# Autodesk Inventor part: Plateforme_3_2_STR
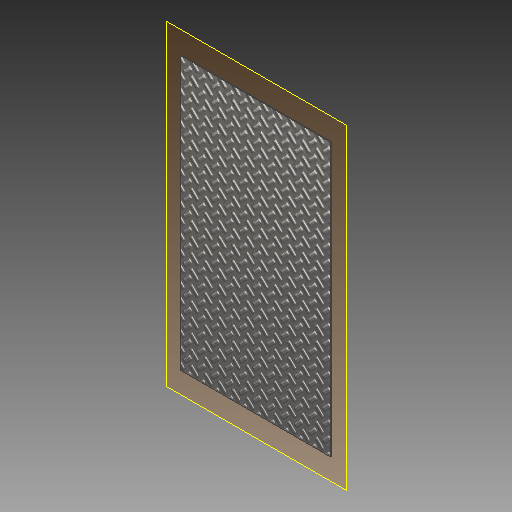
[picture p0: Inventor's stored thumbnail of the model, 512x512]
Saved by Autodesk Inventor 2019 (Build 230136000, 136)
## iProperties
Created: 2018-07
Part Number: Plateforme_3_2_STR
Material: Générique
Document SubType Name: Modeling
Designer: Fabian Perrée
Density: 1 g/cm^3
Appearance: Par défaut
Mass: 7553 g
Surface Area: 30469 cm^2
Volume: 7553 cm^3
Author: Fabian Perrée
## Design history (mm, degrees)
node "Plan de construction1"
sketch "Esquisse1"
  geometry: L1 (1000, 250)-(0, 250) reference; L2 (0, -1500)-(0, 250) reference; L3 (1000, -1500)-(0, -1500) reference; L4 (1000, -1500)-(1000, 250) reference; L5 (45, -1455)-(45, 205); L6 (45, 205)-(955, 205); L7 (955, 205)-(955, -1455); L8 (955, -1455)-(45, -1455)
  constraints: 8 end point, 3 other
  dimensions: "d8" = 45 distance between parallel lines of L3 L8
extrude "Extrusion1" new body sketch "Esquisse1" distance "d0" = 5; taper "d1" = 0 deg
node "Solide1"
node "Référence12"
